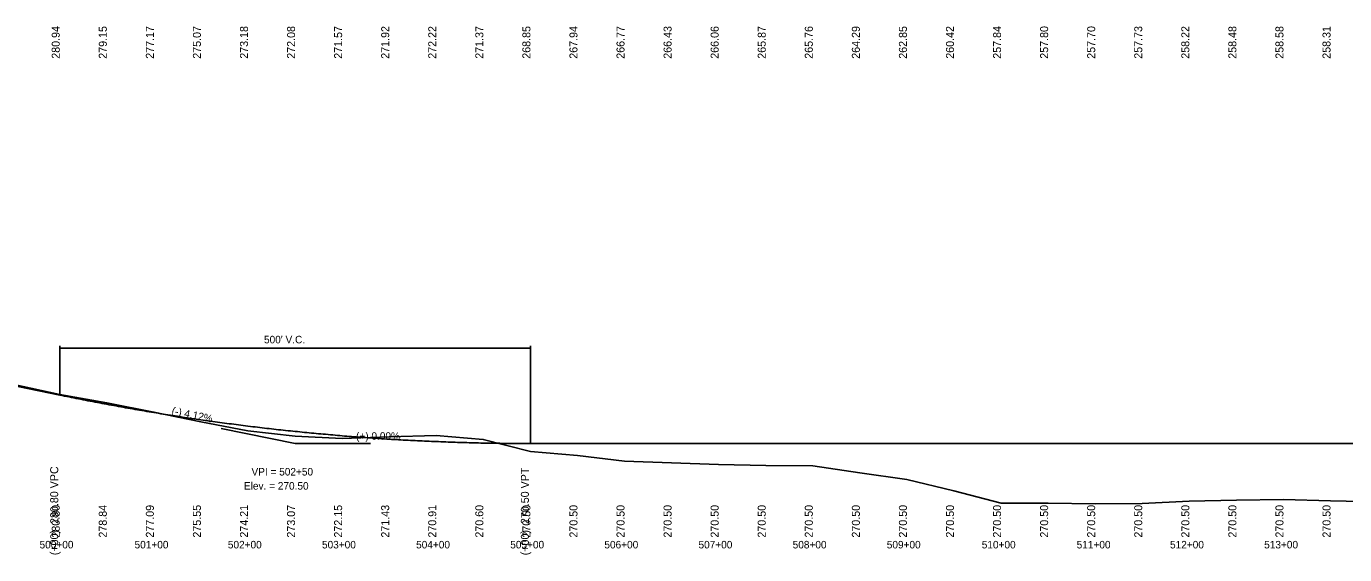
# Model space of a CAD drawing. Extents: x 49241 to 62599, y 49216 to 56011.
# Drawn here: x 58449 to 59849, y 53742 to 54304 of the extents above; entities that cross this region are included whole.
import ezdxf

# ---------------------------------------------------------------- set-up
doc = ezdxf.new("R2010")
doc.units = 0
for name, color, linetype in [('Level 40', 7, 'Continuous'), ('Level 41', 7, 'Continuous'), ('Level 42', 7, 'Continuous'), ('Level 43', 7, 'Continuous'), ('Level 45', 7, 'Continuous')]:
    doc.layers.add(name, color=color, linetype=linetype)

msp = doc.modelspace()

# ---------------------------------------------------------------- linework, layer by layer
at = {"layer": 'Level 40'}
msp.add_lwpolyline([(58434.2, 53923.4), (58484.2, 53912.5), (58534.2, 53903.5), (58584.2, 53893.7), (58634.2, 53883.2), (58684.2, 53873.7), (58734.2, 53868.2), (58784.2, 53865.6), (58834.2, 53867.4), (58884.2, 53868.9), (58934.2, 53864.6), (58984.2, 53852), (59034.2, 53847.5), (59084.2, 53841.6), (59134.2, 53839.9), (59184.2, 53838.1), (59234.2, 53837.1), (59284.2, 53836.6), (59334.2, 53829.2), (59384.2, 53822), (59434.2, 53809.9), (59484.2, 53797), (59534.2, 53796.8), (59584.2, 53796.3), (59634.2, 53796.4), (59684.2, 53798.9), (59734.2, 53800.2), (59784.2, 53800.7), (59834.2, 53799.3), (59884.2, 53798.2)], dxfattribs=at)
at = {"layer": 'Level 41'}
for p, q in [((58484.2, 53964.3), (58484.2, 53911.8)), ((58484.2, 53961.8), (58984.2, 53961.8)), ((58984.2, 53964.3), (58984.2, 53860.3)), ((58655.8, 53876.4), (58734.2, 53860.3)), ((58814.2, 53860.3), (58734.2, 53860.3))]:
    msp.add_line(p, q, dxfattribs=at)
at = {"layer": 'Level 45'}
for p, q in [((58284.2, 53953), (58484.2, 53911.8)), ((58984.2, 53860.3), (61684.2, 53860.3))]:
    msp.add_line(p, q, dxfattribs=at)
msp.add_spline([(58484.2, 53911.8), (58494.2, 53909.8), (58504.2, 53907.8), (58514.2, 53905.8), (58524.2, 53903.9), (58534.2, 53902), (58544.2, 53900.2), (58554.2, 53898.4), (58564.2, 53896.6), (58574.2, 53894.9), (58584.2, 53893.3), (58594.2, 53891.6), (58604.2, 53890), (58614.2, 53888.5), (58624.2, 53887), (58634.2, 53885.5), (58644.2, 53884.1), (58654.2, 53882.7), (58664.2, 53881.4), (58674.2, 53880.1), (58684.2, 53878.8), (58694.2, 53877.6), (58704.2, 53876.4), (58714.2, 53875.3), (58724.2, 53874.2), (58734.2, 53873.2), (58744.2, 53872.2), (58754.2, 53871.2), (58764.2, 53870.3), (58774.2, 53869.4), (58784.2, 53868.5), (58794.2, 53867.7), (58804.2, 53867), (58814.2, 53866.2), (58824.2, 53865.6), (58834.2, 53864.9), (58844.2, 53864.3), (58854.2, 53863.8), (58864.2, 53863.3), (58874.2, 53862.8), (58884.2, 53862.4), (58894.2, 53862), (58904.2, 53861.6), (58914.2, 53861.3), (58924.2, 53861), (58934.2, 53860.8), (58944.2, 53860.6), (58954.2, 53860.5), (58964.2, 53860.4), (58974.2, 53860.3), (58984.2, 53860.3)], degree=3, dxfattribs=at)

# ---------------------------------------------------------------- texts
at = {"layer": 'Level 41'}
for s, p in [("500' V.C.", (58701.2, 53966.8)), ('(+) 0.00%', (58799, 53864.3)), ('VPI = 502+50', (58687.9, 53826.3)), ('Elev. = 270.50', (58679.9, 53811.3))]:
    msp.add_text(s, height=8, dxfattribs=at).set_placement(p)
for s, height, rotation, p in [('(-) 4.12%', 8, 348.3599, (58602.6, 53891.5)), ('(+00)  280.80 VPC', 8.5, 90, (58482.6, 53741.6)), ('(+00)  270.50 VPT', 8.5, 90, (58982.6, 53741.5))]:
    msp.add_text(s, height=height, rotation=rotation, dxfattribs=at).set_placement(p)
at = {"layer": 'Level 42'}
for s, p in [('500+00', (58462.8, 53748.8)), ('501+00', (58563.7, 53748.8)), ('502+00', (58662.8, 53748.8)), ('503+00', (58762.8, 53748.8)), ('504+00', (58862.8, 53748.8)), ('505+00', (58962.8, 53748.8)), ('506+00', (59062.8, 53748.8)), ('507+00', (59162.8, 53748.8)), ('508+00', (59262.8, 53748.8)), ('509+00', (59362.8, 53748.8)), ('510+00', (59463.7, 53748.8)), ('511+00', (59564.5, 53748.8)), ('512+00', (59663.7, 53748.8)), ('513+00', (59763.7, 53748.8))]:
    msp.add_text(s, height=8, dxfattribs=at).set_placement(p)
at = {"layer": 'Level 43'}
for s, p in [('280.94', (58484.2, 54269.3)), ('279.15', (58534.2, 54269.3)), ('277.17', (58584.2, 54269.3)), ('275.07', (58634.2, 54269.3)), ('273.18', (58684.2, 54269.3)), ('272.08', (58734.2, 54269.3)), ('271.57', (58784.2, 54269.3)), ('271.92', (58834.2, 54269.3)), ('272.22', (58884.2, 54269.3)), ('271.37', (58934.2, 54269.3)), ('268.85', (58984.2, 54269.3)), ('267.94', (59034.2, 54269.3)), ('266.77', (59084.2, 54269.3)), ('266.43', (59134.2, 54269.3)), ('266.06', (59184.2, 54269.3)), ('265.87', (59234.2, 54269.3)), ('265.76', (59284.2, 54269.3)), ('264.29', (59334.2, 54269.3)), ('262.85', (59384.2, 54269.3)), ('260.42', (59434.2, 54269.3)), ('257.84', (59484.2, 54269.3)), ('257.80', (59534.2, 54269.3)), ('257.70', (59584.2, 54269.3)), ('257.73', (59634.2, 54269.3)), ('258.22', (59684.2, 54269.3)), ('258.48', (59734.2, 54269.3)), ('258.58', (59784.2, 54269.3)), ('258.31', (59834.2, 54269.3)), ('280.80', (58484.2, 53760.3)), ('278.84', (58534.2, 53760.3)), ('277.09', (58584.2, 53760.3)), ('275.55', (58634.2, 53760.3)), ('274.21', (58684.2, 53760.3)), ('273.07', (58734.2, 53760.3)), ('272.15', (58784.2, 53760.3)), ('271.43', (58834.2, 53760.3)), ('270.91', (58884.2, 53760.3)), ('270.60', (58934.2, 53760.3)), ('270.50', (58984.2, 53760.3)), ('270.50', (59034.2, 53760.3)), ('270.50', (59084.2, 53760.3)), ('270.50', (59134.2, 53760.3)), ('270.50', (59184.2, 53760.3)), ('270.50', (59234.2, 53760.3)), ('270.50', (59284.2, 53760.3)), ('270.50', (59334.2, 53760.3)), ('270.50', (59384.2, 53760.3)), ('270.50', (59434.2, 53760.3)), ('270.50', (59484.2, 53760.3)), ('270.50', (59534.2, 53760.3)), ('270.50', (59584.2, 53760.3)), ('270.50', (59634.2, 53760.3)), ('270.50', (59684.2, 53760.3)), ('270.50', (59734.2, 53760.3)), ('270.50', (59784.2, 53760.3)), ('270.50', (59834.2, 53760.3))]:
    msp.add_text(s, height=8.5, rotation=90, dxfattribs=at).set_placement(p)

doc.saveas('drawing.dxf')
